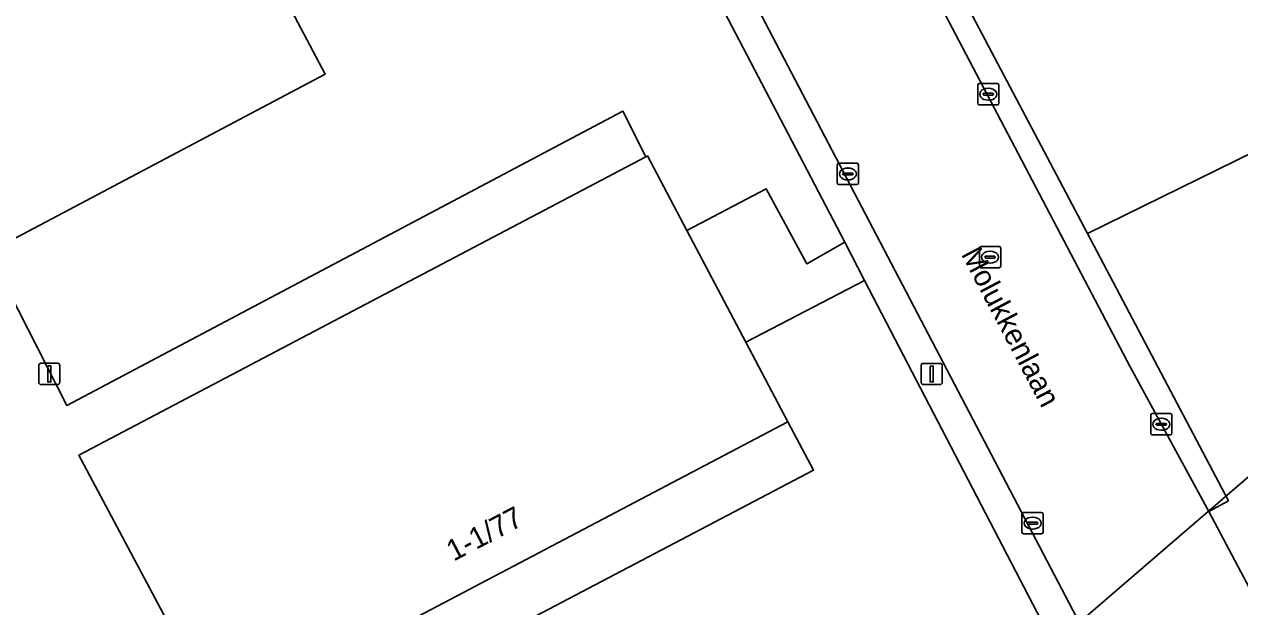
# Model space of a CAD drawing. Extents: x 162879 to 165540, y 384011 to 385181.
# Drawn here: x 163042.9 to 163100.1, y 384191.8 to 384219.2 of the extents above; entities that cross this region are included whole.
import ezdxf

# ---------------------------------------------------------------- set-up
doc = ezdxf.new("R2010")
doc.units = 0
for name, color, linetype in [('IMGEO_Duiker', 7, 'Continuous'), ('IMGEO_Erf', 7, 'Continuous'), ('IMGEO_Groenvoorziening', 7, 'Continuous'), ('IMGEO_Kolk', 7, 'Continuous'), ('IMGEO_Lichtmast', 7, 'Continuous'), ('IMGEO_Openbare_ruimte_label', 7, 'Continuous'), ('IMGEO_Pand', 7, 'Continuous'), ('IMGEO_Pand_nummerreeks', 7, 'Continuous'), ('IMGEO_Parkeervlak_open', 7, 'Continuous'), ('IMGEO_Rijbaan_lokaal_open', 7, 'Continuous'), ('IMGEO_Rioolput', 7, 'Continuous'), ('IMGEO_Voetpad_open', 7, 'Continuous')]:
    doc.layers.add(name, color=color, linetype=linetype)

msp = doc.modelspace()

# ---------------------------------------------------------------- linework, layer by layer
at = {"layer": 'IMGEO_Duiker'}
msp.add_lwpolyline([(163104.732, 384201.517), (163103.836, 384200.746), (163091.422, 384190.068), (163084.3, 384183.942), (163082.614, 384182.492)], dxfattribs=at)
at = {"layer": 'IMGEO_Erf'}
msp.add_lwpolyline([(163102.346, 384234.16), (163102.432, 384234.205), (163100.651, 384237.577), (163103.837, 384239.259), (163105.617, 384235.887), (163105.946, 384236.061), (163097.491, 384250), (163091.662, 384259.624), (163089.311, 384258.655), (163070.929, 384251.083), (163071.501, 384250), (163086.567, 384221.458), (163086.969, 384220.697), (163092.948, 384209.374), (163113.929, 384219.667), (163114.138, 384219.769), (163111.612, 384224.762), (163108.882, 384230.159), (163105.424, 384228.333)], close=True, dxfattribs=at)
at = {"layer": 'IMGEO_Groenvoorziening'}
for points in [[(163136.641, 384247.33), (163114.501, 384233.625), (163114.264, 384226.34), (163117.171, 384220.23), (163116.084, 384217.472), (163113.929, 384219.667), (163092.948, 384209.374), (163099.596, 384196.782), (163098.666, 384196.282), (163103.99, 384186.246), (163104.407, 384185.46), (163109.182, 384176.32), (163111.265, 384178.82), (163114.452, 384185.261), (163114.752, 384186.202), (163115.847, 384189.643), (163116.116, 384192.067), (163116.644, 384196.814), (163123.235, 384199.185), (163132.89, 384203.652)], [(163097.509, 384178.219), (163082.45, 384207.161), (163076.861, 384204.247), (163078.842, 384200.503), (163080.048, 384198.225), (163053.853, 384184.48)]]:
    msp.add_lwpolyline(points, dxfattribs=at)
msp.add_lwpolyline([(163062.352, 384245.606), (163049.969, 384239.189), (163051.264, 384236.696), (163047.577, 384234.747), (163057.039, 384216.873), (163041.173, 384208.482), (163044.864, 384201.274), (163071.063, 384215.12), (163072.147, 384212.977), (163072.222, 384213.017), (163074.076, 384209.512), (163077.812, 384211.477), (163079.73, 384207.94), (163081.516, 384208.957)], close=True, dxfattribs=at)
at = {"layer": 'IMGEO_Kolk'}
for p, q in [((163087.781, 384215.497), (163087.781, 384216.349)), ((163087.856, 384216.423), (163088.708, 384216.423)), ((163088.269, 384216.203), (163088.294, 384216.203)), ((163088.782, 384216.349), (163088.782, 384215.497)), ((163088.04, 384215.917), (163088.04, 384215.929)), ((163088.478, 384215.88), (163088.08, 384215.88)), ((163088.083, 384215.966), (163088.481, 384215.966)), ((163088.292, 384215.643), (163088.267, 384215.643)), ((163088.524, 384215.929), (163088.524, 384215.917)), ((163088.708, 384215.423), (163087.856, 384215.423)), ((163081.241, 384212.67), (163082.093, 384212.67)), ((163081.166, 384211.744), (163081.166, 384212.596)), ((163081.425, 384212.164), (163081.425, 384212.176)), ((163081.863, 384212.127), (163081.465, 384212.127)), ((163081.468, 384212.213), (163081.866, 384212.213)), ((163081.654, 384212.45), (163081.679, 384212.45)), ((163081.909, 384212.176), (163081.909, 384212.164)), ((163082.167, 384212.596), (163082.167, 384211.744)), ((163082.093, 384211.67), (163081.241, 384211.67)), ((163081.677, 384211.89), (163081.652, 384211.89)), ((163095.93, 384199.96), (163095.93, 384200.812)), ((163096.005, 384200.886), (163096.857, 384200.886)), ((163096.418, 384200.666), (163096.443, 384200.666)), ((163096.931, 384200.812), (163096.931, 384199.96)), ((163096.189, 384200.38), (163096.189, 384200.392)), ((163096.627, 384200.343), (163096.229, 384200.343)), ((163096.232, 384200.429), (163096.63, 384200.429)), ((163096.441, 384200.106), (163096.416, 384200.106)), ((163096.673, 384200.392), (163096.673, 384200.38)), ((163096.857, 384199.886), (163096.005, 384199.886)), ((163089.867, 384195.305), (163089.867, 384196.157)), ((163089.942, 384196.231), (163090.794, 384196.231)), ((163090.868, 384196.157), (163090.868, 384195.305)), ((163090.126, 384195.725), (163090.126, 384195.737)), ((163090.564, 384195.688), (163090.166, 384195.688)), ((163090.169, 384195.774), (163090.567, 384195.774)), ((163090.355, 384196.011), (163090.38, 384196.011)), ((163090.61, 384195.737), (163090.61, 384195.725)), ((163090.794, 384195.231), (163089.942, 384195.231)), ((163090.378, 384195.451), (163090.353, 384195.451))]:
    msp.add_line(p, q, dxfattribs=at)
for points in [[(163087.781, 384215.497), (163087.781, 384216.349)], [(163087.856, 384216.423), (163088.708, 384216.423)], [(163088.782, 384216.349), (163088.782, 384215.497)], [(163088.708, 384215.423), (163087.856, 384215.423)], [(163081.241, 384212.67), (163082.093, 384212.67)], [(163081.166, 384211.744), (163081.166, 384212.596)], [(163082.167, 384212.596), (163082.167, 384211.744)], [(163082.093, 384211.67), (163081.241, 384211.67)], [(163095.93, 384199.96), (163095.93, 384200.812)], [(163096.005, 384200.886), (163096.857, 384200.886)], [(163096.931, 384200.812), (163096.931, 384199.96)], [(163096.857, 384199.886), (163096.005, 384199.886)], [(163089.867, 384195.305), (163089.867, 384196.157)], [(163089.942, 384196.231), (163090.794, 384196.231)], [(163090.868, 384196.157), (163090.868, 384195.305)], [(163090.794, 384195.231), (163089.942, 384195.231)]]:
    msp.add_lwpolyline(points, dxfattribs=at)
for centre, radius, start, end in [((163087.858, 384216.347), 0.0765, 91.552, 178.448), ((163087.858, 384216.347), 0.0765, 91.552, 178.448), ((163088.706, 384216.347), 0.0765, 1.552, 88.448), ((163088.706, 384216.347), 0.0765, 1.552, 88.448), ((163088.08, 384215.926), 0.0403, 85.8775, 175.7526), ((163088.077, 384215.916), 0.0366, 178.938, 274.7102), ((163088.481, 384215.923), 0.043, 264.8664, 352.4533), ((163088.485, 384215.928), 0.0386, 1.7309, 96.639), ((163087.858, 384215.499), 0.0765, 181.552, 268.448), ((163087.858, 384215.499), 0.0765, 181.552, 268.448), ((163088.706, 384215.499), 0.0765, 271.552, 358.448), ((163088.706, 384215.499), 0.0765, 271.552, 358.448), ((163081.243, 384212.594), 0.0765, 91.552, 178.448), ((163081.243, 384212.594), 0.0765, 91.552, 178.448), ((163082.091, 384212.594), 0.0765, 1.552, 88.448), ((163082.091, 384212.594), 0.0765, 1.552, 88.448), ((163081.465, 384212.173), 0.0403, 85.8775, 175.7526), ((163081.462, 384212.163), 0.0366, 178.938, 274.7102), ((163081.866, 384212.17), 0.043, 264.8664, 352.4533), ((163081.87, 384212.175), 0.0386, 1.7309, 96.639), ((163081.243, 384211.746), 0.0765, 181.552, 268.448), ((163081.243, 384211.746), 0.0765, 181.552, 268.448), ((163082.091, 384211.746), 0.0765, 271.552, 358.448), ((163082.091, 384211.746), 0.0765, 271.552, 358.448), ((163096.007, 384200.81), 0.0765, 91.552, 178.448), ((163096.007, 384200.81), 0.0765, 91.552, 178.448), ((163096.855, 384200.81), 0.0765, 1.552, 88.448), ((163096.855, 384200.81), 0.0765, 1.552, 88.448), ((163096.229, 384200.389), 0.0403, 85.8775, 175.7526), ((163096.226, 384200.379), 0.0366, 178.938, 274.7102), ((163096.63, 384200.386), 0.043, 264.8664, 352.4533), ((163096.634, 384200.391), 0.0386, 1.7309, 96.639), ((163096.007, 384199.962), 0.0765, 181.552, 268.448), ((163096.007, 384199.962), 0.0765, 181.552, 268.448), ((163096.855, 384199.962), 0.0765, 271.552, 358.448), ((163096.855, 384199.962), 0.0765, 271.552, 358.448), ((163089.944, 384196.155), 0.0765, 91.552, 178.448), ((163089.944, 384196.155), 0.0765, 91.552, 178.448), ((163090.792, 384196.155), 0.0765, 1.552, 88.448), ((163090.792, 384196.155), 0.0765, 1.552, 88.448), ((163090.166, 384195.734), 0.0403, 85.8775, 175.7526), ((163090.163, 384195.724), 0.0366, 178.938, 274.7102), ((163090.567, 384195.731), 0.043, 264.8664, 352.4533), ((163090.571, 384195.736), 0.0386, 1.7309, 96.639), ((163089.944, 384195.307), 0.0765, 181.552, 268.448), ((163089.944, 384195.307), 0.0765, 181.552, 268.448), ((163090.792, 384195.307), 0.0765, 271.552, 358.448), ((163090.792, 384195.307), 0.0765, 271.552, 358.448)]:
    msp.add_arc(centre, radius, start, end, dxfattribs=at)
for centre, major_axis, ratio, start_param, end_param in [((163088.268, 384215.923), (-0.387, 0.002), 0.722429, 4.712389, 7.853982), ((163088.293, 384215.923), (-0.39, 0.002), 0.717154, 1.570796, 4.712389), ((163081.653, 384212.17), (-0.387, 0.002), 0.722429, 4.712389, 7.853982), ((163081.678, 384212.17), (-0.39, 0.002), 0.717154, 1.570796, 4.712389), ((163096.417, 384200.386), (-0.387, 0.002), 0.722429, 4.712389, 7.853982), ((163096.442, 384200.386), (-0.39, 0.002), 0.717154, 1.570796, 4.712389), ((163090.354, 384195.731), (-0.387, 0.002), 0.722429, 4.712389, 7.853982), ((163090.379, 384195.731), (-0.39, 0.002), 0.717154, 1.570796, 4.712389)]:
    msp.add_ellipse(centre, major_axis=major_axis, ratio=ratio, start_param=start_param, end_param=end_param, dxfattribs=at)
at = {"layer": 'IMGEO_Lichtmast'}
for p, q in [((163043.547, 384202.358), (163043.547, 384203.158)), ((163043.547, 384203.158), (163043.547, 384202.358)), ((163043.647, 384203.258), (163044.437, 384203.258)), ((163044.437, 384203.258), (163043.647, 384203.258)), ((163044.537, 384203.158), (163044.537, 384202.358)), ((163044.537, 384202.358), (163044.537, 384203.158)), ((163085.118, 384202.353), (163085.118, 384203.153)), ((163085.118, 384203.153), (163085.118, 384202.353)), ((163085.218, 384203.253), (163086.008, 384203.253)), ((163086.008, 384203.253), (163085.218, 384203.253)), ((163086.108, 384203.153), (163086.108, 384202.353)), ((163086.108, 384202.353), (163086.108, 384203.153)), ((163044.437, 384202.258), (163043.647, 384202.258)), ((163043.647, 384202.258), (163044.437, 384202.258)), ((163086.008, 384202.253), (163085.218, 384202.253)), ((163085.218, 384202.253), (163086.008, 384202.253))]:
    msp.add_line(p, q, dxfattribs=at)
for points in [[(163043.967, 384203.133), (163044.117, 384203.133), (163044.117, 384202.383), (163043.967, 384202.383), (163043.967, 384203.133)], [(163085.538, 384203.128), (163085.688, 384203.128), (163085.688, 384202.378), (163085.538, 384202.378), (163085.538, 384203.128)]]:
    msp.add_lwpolyline(points, dxfattribs=at)
for centre, start, end in [((163043.647, 384203.158), 90, 180), ((163043.647, 384203.158), 90, 180), ((163044.437, 384203.158), 0, 90), ((163044.437, 384203.158), 360, 90), ((163085.218, 384203.153), 90, 180), ((163085.218, 384203.153), 90, 180), ((163086.008, 384203.153), 0, 90), ((163086.008, 384203.153), 360, 90), ((163043.647, 384202.358), 180, 270), ((163043.647, 384202.358), 180, 270), ((163044.437, 384202.358), 270, 0), ((163044.437, 384202.358), 270, 0), ((163085.218, 384202.353), 180, 270), ((163085.218, 384202.353), 180, 270), ((163086.008, 384202.353), 270, 0), ((163086.008, 384202.353), 270, 0)]:
    msp.add_arc(centre, 0.1, start, end, dxfattribs=at)
at = {"layer": 'IMGEO_Pand'}
msp.add_lwpolyline([(163078.842, 384200.503), (163076.861, 384204.247), (163074.076, 384209.512), (163072.222, 384213.017), (163072.147, 384212.977), (163045.43, 384198.93), (163052.096, 384186.437)], close=True, dxfattribs=at)
at = {"layer": 'IMGEO_Parkeervlak_open'}
msp.add_lwpolyline([(163057.039, 384216.873), (163047.577, 384234.747), (163046.764, 384236.284), (163042.428, 384234.014), (163041.974, 384234.886), (163036.667, 384232.088), (163037.115, 384231.211), (163032.652, 384228.845), (163041.946, 384211.188), (163040.222, 384210.272), (163041.173, 384208.482)], close=True, dxfattribs=at)
at = {"layer": 'IMGEO_Rijbaan_lokaal_open'}
for points in [[(163068.997, 384247.911), (163064.184, 384245.26), (163065.688, 384242.421), (163067.65, 384238.621), (163098.898, 384178.954), (163107.986, 384161.625), (163108.767, 384160.138)], [(163123.456, 384148.995), (163120.518, 384154.619), (163109.182, 384176.32), (163104.407, 384185.46), (163103.99, 384186.246), (163098.666, 384196.282), (163094.956, 384203.096), (163085.593, 384220.946), (163078.99, 384233.534), (163074.347, 384242.176), (163072.969, 384244.801), (163072.377, 384245.947)], [(163053.853, 384184.48), (163080.048, 384198.225), (163078.842, 384200.503), (163052.096, 384186.437), (163045.43, 384198.93), (163072.147, 384212.977), (163071.063, 384215.12), (163044.864, 384201.274), (163041.173, 384208.482)]]:
    msp.add_lwpolyline(points, dxfattribs=at)
at = {"layer": 'IMGEO_Rioolput'}
for p, q in [((163087.863, 384207.828), (163087.863, 384208.68)), ((163087.938, 384208.754), (163088.79, 384208.754)), ((163088.864, 384208.68), (163088.864, 384207.828)), ((163088.122, 384208.248), (163088.122, 384208.26)), ((163088.56, 384208.211), (163088.162, 384208.211)), ((163088.165, 384208.297), (163088.563, 384208.297)), ((163088.351, 384208.534), (163088.376, 384208.534)), ((163088.606, 384208.26), (163088.606, 384208.248)), ((163088.79, 384207.754), (163087.938, 384207.754)), ((163088.374, 384207.974), (163088.349, 384207.974))]:
    msp.add_line(p, q, dxfattribs=at)
for points in [[(163087.863, 384207.828), (163087.863, 384208.68)], [(163087.938, 384208.754), (163088.79, 384208.754)], [(163088.864, 384208.68), (163088.864, 384207.828)], [(163088.79, 384207.754), (163087.938, 384207.754)]]:
    msp.add_lwpolyline(points, dxfattribs=at)
for centre, radius, start, end in [((163087.94, 384208.678), 0.0765, 91.552, 178.448), ((163087.94, 384208.678), 0.0765, 91.552, 178.448), ((163088.788, 384208.678), 0.0765, 1.552, 88.448), ((163088.788, 384208.678), 0.0765, 1.552, 88.448), ((163088.162, 384208.257), 0.0403, 85.8775, 175.7526), ((163088.159, 384208.247), 0.0366, 178.938, 274.7102), ((163088.563, 384208.254), 0.043, 264.8664, 352.4533), ((163088.567, 384208.259), 0.0386, 1.7309, 96.639), ((163087.94, 384207.83), 0.0765, 181.552, 268.448), ((163087.94, 384207.83), 0.0765, 181.552, 268.448), ((163088.788, 384207.83), 0.0765, 271.552, 358.448), ((163088.788, 384207.83), 0.0765, 271.552, 358.448)]:
    msp.add_arc(centre, radius, start, end, dxfattribs=at)
for centre, major_axis, ratio, start_param, end_param in [((163088.35, 384208.254), (-0.387, 0.002), 0.722429, 4.712389, 7.853982), ((163088.375, 384208.254), (-0.39, 0.002), 0.717154, 1.570796, 4.712389)]:
    msp.add_ellipse(centre, major_axis=major_axis, ratio=ratio, start_param=start_param, end_param=end_param, dxfattribs=at)
at = {"layer": 'IMGEO_Voetpad_open'}
for points in [[(163067.65, 384238.621), (163065.688, 384242.421), (163064.184, 384245.26), (163062.352, 384245.606), (163081.516, 384208.957), (163082.45, 384207.161), (163097.509, 384178.219), (163099.858, 384173.768), (163108.593, 384157.219), (163108.822, 384157.894)], [(163108.767, 384160.138), (163107.986, 384161.625), (163098.898, 384178.954), (163067.65, 384238.621)]]:
    msp.add_lwpolyline(points, dxfattribs=at)
for points in [[(163092.948, 384209.374), (163086.969, 384220.697), (163086.567, 384221.458), (163085.593, 384220.946), (163094.956, 384203.096), (163098.666, 384196.282), (163099.596, 384196.782)], [(163081.516, 384208.957), (163079.73, 384207.94), (163077.812, 384211.477), (163074.076, 384209.512), (163076.861, 384204.247), (163082.45, 384207.161)]]:
    msp.add_lwpolyline(points, close=True, dxfattribs=at)

# ---------------------------------------------------------------- texts
at = {"layer": 'IMGEO_Openbare_ruimte_label'}
msp.add_text('Molukkenlaan', height=1, rotation=297.7692, dxfattribs=at).set_placement((163086.98, 384208.399))
at = {"layer": 'IMGEO_Pand_nummerreeks'}
msp.add_text('1-1/77', height=1, rotation=27.7426, dxfattribs=at).set_placement((163063.09, 384193.914))

doc.saveas('drawing.dxf')
